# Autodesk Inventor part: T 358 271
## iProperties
Created: 2005-10
Part Number: T 358 271
Material: 1.0718.07
Document SubType Name: Modeling
Designer: I.Baliuc
Manufacturer: Standard
Standards Organization: Custom
Description: Schaltscheibe, links
Density: 7.84 g/cm^3
Title: Schaltscheibe, links
Company: Mayer & Müller AG Schaltgeräte
Abmessung: Rd 80
HalbzeugNorm: DIN 671
Zweck: Trenner HSE / HSD
Author: T.Messerschmitt
Revision Number: 358271
Keywords: 380098
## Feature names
1. Drehung1 [Revolution]
2. Extrusion2
3. Bohrung_M12 [Hole]
4. Ankörnung [Hole]
